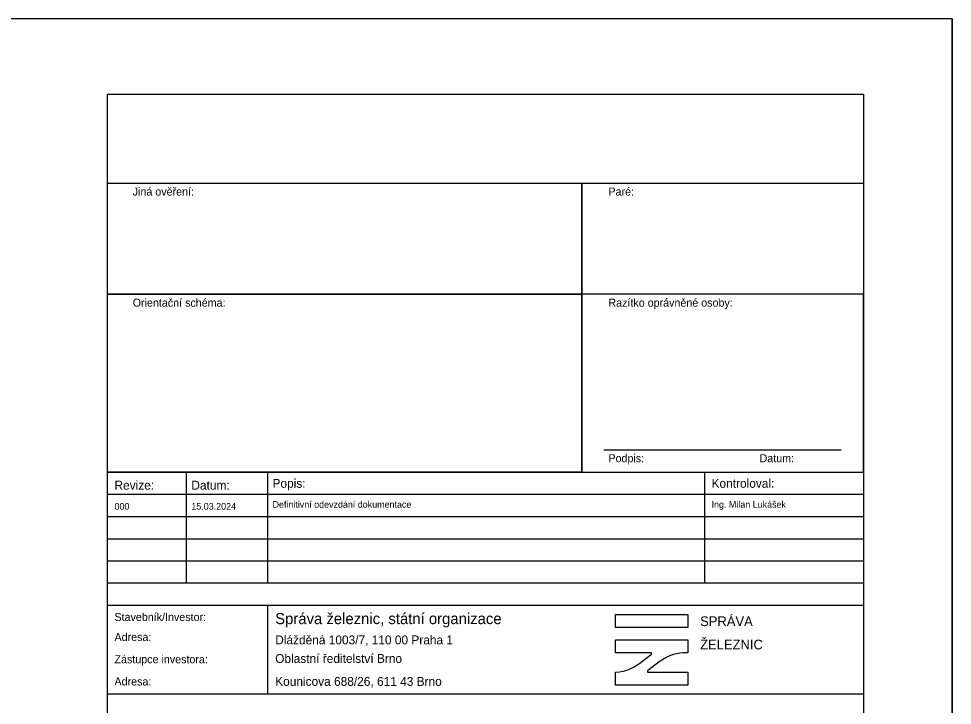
# Model space of a CAD drawing. Extents: x -193 to -151, y 333 to 362.7.
# Drawn here: x -172 to -151, y 347.25 to 362.7 of the extents above; entities that cross this region are included whole.
import ezdxf

# ---------------------------------------------------------------- set-up
doc = ezdxf.new("R2010")
doc.units = 0
for name, color, linetype in [('Default', 7, 'Continuous'), ('Rozpiska_Logo', 7, 'Continuous'), ('Rozpiska_pola_3', 7, 'Continuous'), ('Rozpiska_pole_1', 7, 'Continuous'), ('Rozpiska_pole_2', 7, 'Continuous'), ('Rozpiska_pole_4', 7, 'Continuous'), ('Rozpiska_pole_5', 7, 'Continuous'), ('Rozpiska_pole_6', 7, 'Continuous')]:
    doc.layers.add(name, color=color, linetype=linetype)

msp = doc.modelspace()

# ---------------------------------------------------------------- linework, layer by layer
at = {"layer": 'Default'}
for p, q in [((-151, 362.7), (-151, 333)), ((-159.335, 352.5), (-159.335, 359))]:
    msp.add_line(p, q, dxfattribs=at)
msp.add_lwpolyline([(-193, 333), (-151, 333), (-151, 362.7), (-193, 362.7)], close=True, dxfattribs=at)
at = {"layer": 'Rozpiska_Logo'}
for p, q in [((-157.96, 348.253), (-157.766, 348.399)), ((-157.766, 348.399), (-157.766, 348.434)), ((-157.597, 348.226), (-157.858, 348.024)), ((-157.858, 348.024), (-157.858, 347.993))]:
    msp.add_line(p, q, dxfattribs=at)
msp.add_lwpolyline([(-158.578, 349.291), (-156.948, 349.291), (-156.948, 348.998), (-158.578, 348.998)], close=True, dxfattribs=at)
for points in [[(-157.766, 348.434), (-158.578, 348.434), (-158.578, 348.727), (-156.948, 348.727), (-156.948, 348.434), (-157.056, 348.434)], [(-157.858, 347.993), (-156.948, 347.993), (-156.948, 347.7), (-158.578, 347.7), (-158.578, 347.993), (-158.572, 347.993)]]:
    msp.add_lwpolyline(points, dxfattribs=at)
for centre, radius, start, end in [((-156.982, 347.432), 1.004, 94.2142, 127.7808), ((-158.656, 349.042), 1.052, 274.6014, 311.4254)]:
    msp.add_arc(centre, radius, start, end, dxfattribs=at)
at = {"layer": 'Rozpiska_pola_3'}
msp.add_line((-158.835, 353), (-153.5, 353), dxfattribs=at)
at = {"layer": 'Rozpiska_pole_1'}
msp.add_lwpolyline([(-170, 361), (-153, 361), (-153, 334.5), (-170, 334.5)], close=True, dxfattribs=at)
at = {"layer": 'Rozpiska_pole_2'}
for points in [[(-170, 359), (-159.335, 359), (-159.335, 356.5), (-170, 356.5)], [(-159.335, 359), (-153, 359), (-153, 356.5), (-159.335, 356.5)], [(-170, 356.5), (-159.335, 356.5), (-159.335, 352.5), (-170, 352.5)], [(-153, 356.5), (-159.335, 356.5), (-159.335, 352.5), (-153, 352.5)]]:
    msp.add_lwpolyline(points, close=True, dxfattribs=at)
at = {"layer": 'Rozpiska_pole_4'}
for p, q in [((-168.223, 350), (-168.223, 352.5)), ((-166.395, 350), (-166.395, 352.5)), ((-156.57, 350), (-156.57, 352.5)), ((-170, 352), (-153, 352)), ((-170, 351.5), (-153, 351.5)), ((-170, 351), (-153, 351)), ((-170, 350.5), (-153, 350.5))]:
    msp.add_line(p, q, dxfattribs=at)
msp.add_lwpolyline([(-170, 352.5), (-153, 352.5), (-153, 350), (-170, 350)], close=True, dxfattribs=at)
at = {"layer": 'Rozpiska_pole_5'}
msp.add_line((-166.395, 347.5), (-166.395, 349.5), dxfattribs=at)
msp.add_lwpolyline([(-170, 349.5), (-153, 349.5), (-153, 347.5), (-170, 347.5)], close=True, dxfattribs=at)

# ---------------------------------------------------------------- texts
at = {"layer": 'Rozpiska_pola_3'}
for s, p in [('Paré:', (-158.735, 358.72)), ('Razítko oprávněné osoby:', (-158.735, 356.22)), ('Podpis:', (-158.735, 352.72)), ('Datum:', (-155.335, 352.72))]:
    msp.add_text(s, height=0.18, dxfattribs=at).set_placement(p)
at = {"layer": 'Rozpiska_pole_2'}
for s, p in [('Jiná ověření:', (-169.435, 358.72)), ('Orientační schéma:', (-169.435, 356.22))]:
    msp.add_text(s, height=0.18, dxfattribs=at).set_placement(p)
at = {"layer": 'Rozpiska_pole_4'}
for s, height, p in [('Revize:', 0.2, (-169.845, 352.103)), ('Datum:', 0.2, (-168.116, 352.103)), ('Popis:', 0.2, (-166.29, 352.145)), ('Kontroloval:', 0.2, (-156.415, 352.145)), ('000', 0.15, (-169.845, 351.653)), ('15.03.2024', 0.15, (-168.116, 351.653)), ('Definitivní odevzdání dokumentace', 0.15, (-166.29, 351.695)), ('Ing. Milan Lukášek', 0.15, (-156.415, 351.695))]:
    msp.add_text(s, height=height, dxfattribs=at).set_placement(p)
at = {"layer": 'Rozpiska_pole_5'}
for s, height, p in [('Stavebník/Investor:', 0.18, (-169.845, 349.147)), ('Správa železnic, státní organizace', 0.25, (-166.23, 349.077)), ('Adresa:', 0.18, (-169.845, 348.697)), ('Zástupce investora:', 0.18, (-169.845, 348.197)), ('Adresa:', 0.18, (-169.845, 347.697))]:
    msp.add_text(s, height=height, dxfattribs=at).set_placement(p)
at = {"layer": 'Rozpiska_pole_6'}
for s, height, p in [('SPRÁVA', 0.2183, (-156.673, 349.033)), ('Dlážděná 1003/7, 110 00 Praha 1', 0.2, (-166.23, 348.622)), ('ŽELEZNIC', 0.2183, (-156.673, 348.509)), ('Oblastní ředitelství Brno', 0.2, (-166.23, 348.204)), ('Kounicova 688/26, 611 43 Brno', 0.2, (-166.23, 347.688))]:
    msp.add_text(s, height=height, dxfattribs=at).set_placement(p)

doc.saveas('drawing.dxf')
